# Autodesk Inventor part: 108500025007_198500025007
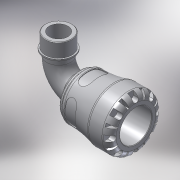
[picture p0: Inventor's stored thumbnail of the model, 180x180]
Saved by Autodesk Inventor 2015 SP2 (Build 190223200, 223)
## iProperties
Created: 2016-12
Part Number: 108500025007_198500025007
Material: PVC-Piping
Description: PLASSON 90° ELBOW WITH THREADED MALE OFFTAKE 25X3/4" SERIES 1
Document SubType Name: Modeling
Designer: KIM
Mass: 91.9364 g
Surface Area: 226.145 cm^2
Volume: 65.6689 cm^3
Density: 1.4 g/cm^3
Appearance: Smooth - White
Author: KIM
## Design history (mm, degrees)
derived "1085.ipt"
feature "Solid1::1085.ipt"
tag "TaggingFeature1"
body "Solid1"
other parameters: "d1" = 20.16, "d2" = 25, "d3" = 31.25, "d4" = 47, "d8" = 39.95, "d13" = 6.3, "d14" = 6.3, "d15" = 0, "d17" = 360 deg, "d19" = 8 deg, "d20" = 0.5, "d21" = 0.5, "d22" = 8 deg, "d24" = 0, "d26" = 360 deg, "d33" = 4.7, "d43" = 36.66, "d51" = 0.47, "d54" = 8.75, "d55" = 5.5, "d57" = 12.348, "d58" = 0, "d74" = 0, "d78" = 48, "d82" = 0.5, "d115" = 360 deg, "d207" = 90 deg, "d228" = 7.4375, "d247" = 0.94, "d248" = 2.88, "d268" = 21.9725, "d269" = 2.88, "d270" = 74, "d276" = 26.441, "d277" = 17, "d278" = 29.0851, "d279" = 45, "d280" = 18.7, "d281" = 3.96615, "d283" = 23.7969, "d286" = 0, "d287" = 0, "d288" = 18.5087, "d290" = 6.43155, "d292" = 30 deg, "d_" = 25, "E_" = 47, "l_" = 48, "A_" = 74, "A_1" = 45, "l_2" = 17, "R_" = 26.441, "d9" = 7.875, "d11" = 47, "d12" = 31.25, "d289" = 18.5087
